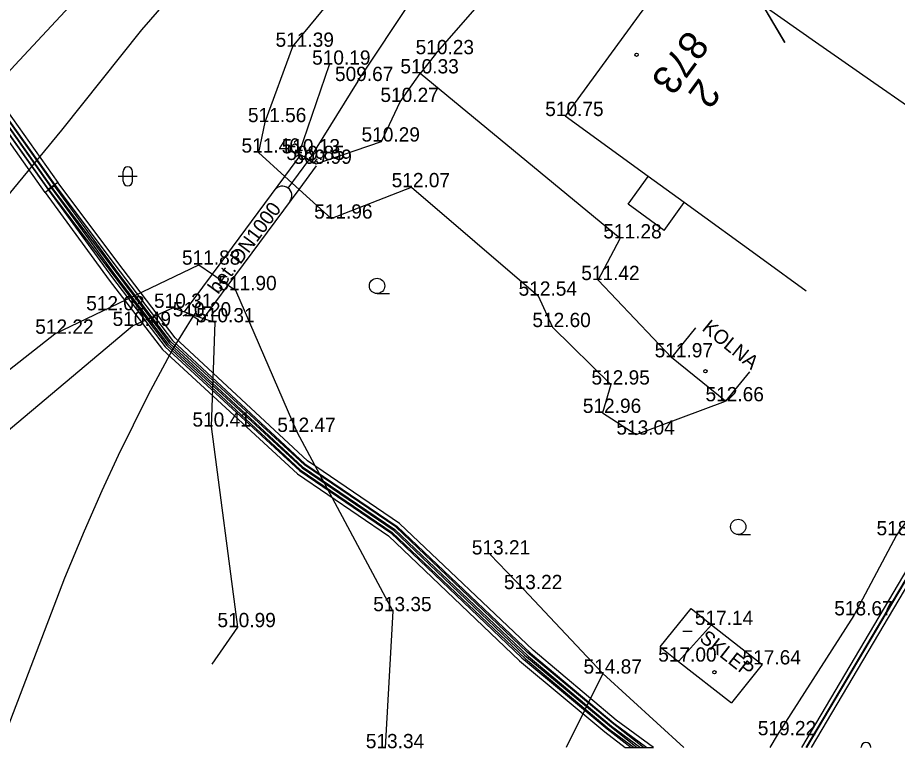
# Model space of a CAD drawing. Extents: x -669642 to -669119, y -1131006 to -1130466.
# Drawn here: x -669445.4 to -669399.17, y -1131000.64 to -1130962.24 of the extents above; entities that cross this region are included whole.
import ezdxf

# ---------------------------------------------------------------- set-up
doc = ezdxf.new("R2010")
doc.units = 0
for name, color, linetype in [('G_Bod_tecka', 7, 'Continuous'), ('G_Bod_vyska', 7, 'Continuous'), ('G_Breh_Teren', 7, 'Continuous'), ('G_Budovy-znacky', 7, 'Continuous'), ('G_Budovy_Objekty', 7, 'Continuous'), ('G_Budovy_vstupy', 7, 'Continuous'), ('G_Cesty_Schody', 7, 'Continuous'), ('G_Cisla_orientacni', 7, 'Continuous'), ('G_Cisla_popisna', 7, 'Continuous'), ('G_Ploty', 7, 'Continuous'), ('G_Ploty_vstupy', 7, 'Continuous'), ('G_Popisy_objektu', 7, 'Continuous'), ('G_Poznamky_odkaz', 7, 'Continuous'), ('G_Site-kanalizace', 7, 'Continuous'), ('G_Z_CHRANICKA-TEPLOVOD_kotovane', 7, 'Continuous'), ('G_Z_ELsilove_podz_kotovane', 7, 'Continuous'), ('G_Z_SPOJE_podz_kotovane', 7, 'Continuous'), ('G_Z_VODA_podz_kotovane', 7, 'Continuous'), ('G_Zelen-Znacky', 7, 'Continuous'), ('Vrstva 26', 7, 'Continuous')]:
    doc.layers.add(name, color=color, linetype=linetype)

msp = doc.modelspace()

# ---------------------------------------------------------------- linework, layer by layer
at = {"layer": 'G_Bod_tecka'}
for p, q in [((-669430.96, -1130963.77), (-669430.96, -1130963.77)), ((-669423.44, -1130964.16), (-669423.44, -1130964.16)), ((-669429.02, -1130964.71), (-669429.02, -1130964.71)), ((-669424.24, -1130965.17), (-669424.24, -1130965.17)), ((-669427.52, -1130965.57), (-669427.52, -1130965.57)), ((-669425.29, -1130966.67), (-669425.29, -1130966.67)), ((-669416.63, -1130967.41), (-669416.63, -1130967.41)), ((-669432.4, -1130967.73), (-669432.4, -1130967.73)), ((-669426.28, -1130968.75), (-669426.28, -1130968.75)), ((-669432.74, -1130969.33), (-669432.74, -1130969.33)), ((-669430.62, -1130969.37), (-669430.62, -1130969.37)), ((-669430.09, -1130969.72), (-669430.09, -1130969.72)), ((-669429.71, -1130969.92), (-669429.71, -1130969.92)), ((-669424.7, -1130971.15), (-669424.7, -1130971.15)), ((-669428.92, -1130972.8), (-669428.92, -1130972.8)), ((-669413.74, -1130973.84), (-669413.74, -1130973.84)), ((-669435.88, -1130975.22), (-669435.88, -1130975.22)), ((-669414.9, -1130976.03), (-669414.9, -1130976.03)), ((-669433.95, -1130976.56), (-669433.95, -1130976.56)), ((-669418.05, -1130976.85), (-669418.05, -1130976.85)), ((-669440.75, -1130977.62), (-669440.75, -1130977.62)), ((-669437.25, -1130977.49), (-669437.25, -1130977.49)), ((-669436.18, -1130977.94), (-669436.18, -1130977.94)), ((-669439.36, -1130978.44), (-669439.36, -1130978.44)), ((-669435.03, -1130978.25), (-669435.03, -1130978.25)), ((-669417.29, -1130978.5), (-669417.29, -1130978.5)), ((-669443.45, -1130978.85), (-669443.45, -1130978.85)), ((-669411.04, -1130980.09), (-669411.04, -1130980.09)), ((-669414.22, -1130981.52), (-669414.22, -1130981.52)), ((-669408.2, -1130982.4), (-669408.2, -1130982.4)), ((-669414.66, -1130983.01), (-669414.66, -1130983.01)), ((-669435.23, -1130983.73), (-669435.23, -1130983.73)), ((-669430.73, -1130984.01), (-669430.73, -1130984.01)), ((-669412.89, -1130984.15), (-669412.89, -1130984.15)), ((-669399.22, -1130989.44), (-669399.22, -1130989.44)), ((-669420.57, -1130990.45), (-669420.57, -1130990.45)), ((-669418.82, -1130992.27), (-669418.82, -1130992.27)), ((-669425.69, -1130993.43), (-669425.69, -1130993.43)), ((-669401.45, -1130993.65), (-669401.45, -1130993.65)), ((-669433.85, -1130994.27), (-669433.85, -1130994.27)), ((-669408.93, -1130994.15), (-669408.93, -1130994.15)), ((-669410.67, -1130996.08), (-669410.67, -1130996.08)), ((-669406.27, -1130996.23), (-669406.27, -1130996.23)), ((-669414.64, -1130996.71), (-669414.64, -1130996.71)), ((-669405.48, -1130999.95), (-669405.48, -1130999.95))]:
    msp.add_line(p, q, dxfattribs=at)
at = {"layer": 'G_Breh_Teren'}
for p, q in [((-669427.52, -1130965.57), (-669419.21, -1130953.1)), ((-669430.96, -1130963.77), (-669432.4, -1130967.73)), ((-669429.02, -1130964.71), (-669430.62, -1130969.37)), ((-669425.29, -1130966.67), (-669424.24, -1130965.17)), ((-669427.52, -1130965.57), (-669430.08, -1130969.7)), ((-669426.28, -1130968.75), (-669425.29, -1130966.67)), ((-669429.71, -1130969.92), (-669426.28, -1130968.75)), ((-669430.62, -1130969.37), (-669430.51, -1130969.44)), ((-669430.51, -1130969.44), (-669430.08, -1130969.7)), ((-669430.08, -1130969.7), (-669429.71, -1130969.92)), ((-669431.36, -1130970.59), (-669430.61, -1130971.27)), ((-669428.92, -1130972.8), (-669424.7, -1130971.15)), ((-669424.7, -1130971.15), (-669418.05, -1130976.85)), ((-669430.61, -1130971.27), (-669428.92, -1130972.8)), ((-669418.05, -1130976.85), (-669417.29, -1130978.5)), ((-669417.29, -1130978.5), (-669414.22, -1130981.52)), ((-669414.22, -1130981.52), (-669414.66, -1130983.01)), ((-669412.89, -1130984.15), (-669408.2, -1130982.4)), ((-669414.66, -1130983.01), (-669412.89, -1130984.15)), ((-669414.64, -1130996.71), (-669416.569, -1131000.6))]:
    msp.add_line(p, q, dxfattribs=at)
for points in [[(-669430.96, -1130963.77), (-669421.02, -1130951.72)], [(-669435.92, -1130954.59), (-669439.18, -1130957.99), (-669442.43, -1130961.39), (-669445.54, -1130964.74), (-669448.62, -1130968.12), (-669451.09, -1130970.63), (-669452.47, -1130971.73), (-669454.01, -1130972.63), (-669454.91, -1130972.96), (-669456.53, -1130973.24), (-669459.04, -1130973.32), (-669460.28, -1130973.4), (-669461.49, -1130973.64), (-669462.64, -1130973.98), (-669463.8, -1130974.32)], [(-669434.28, -1130957.66), (-669435.12, -1130958.57), (-669435.95, -1130959.48), (-669438.89, -1130962.88), (-669443.1, -1130968.15), (-669447.41, -1130973.39), (-669448.41, -1130974.47), (-669449.22, -1130975.22), (-669450.54, -1130976.2), (-669452.04, -1130976.89), (-669453.39, -1130977.17), (-669455.45, -1130977.27), (-669456.48, -1130977.33), (-669457.49, -1130977.5), (-669458.81, -1130977.82), (-669460.13, -1130978.14)], [(-669432.4, -1130967.73), (-669432.74, -1130969.33)], [(-669432.74, -1130969.33), (-669431.36, -1130970.59)], [(-669443.45, -1130978.85), (-669435.88, -1130975.22)], [(-669435.88, -1130975.22), (-669435.16, -1130975.72)], [(-669435.16, -1130975.72), (-669434.33, -1130976.29)], [(-669434.33, -1130976.29), (-669433.95, -1130976.56)], [(-669433.95, -1130976.56), (-669430.73, -1130984.01)], [(-669439.36, -1130978.44), (-669437.25, -1130977.49)], [(-669437.25, -1130977.49), (-669436.63, -1130977.7)], [(-669436.63, -1130977.7), (-669435.63, -1130978.04)], [(-669446.319, -1131000.6), (-669442.91, -1130991.68), (-669441.88, -1130989.21), (-669440.95, -1130987.08), (-669440.1, -1130985.23), (-669438.52, -1130982.04), (-669437.26, -1130979.7), (-669436.18, -1130977.94)], [(-669435.63, -1130978.04), (-669435.03, -1130978.25)], [(-669464.693, -1131000.6), (-669460.18, -1130996.71), (-669458.38, -1130995.11), (-669455.74, -1130992.64), (-669454.45, -1130991.37), (-669453.2, -1130990.07), (-669439.36, -1130978.44)], [(-669435.03, -1130978.25), (-669435.23, -1130983.73)], [(-669469.073, -1131000.6), (-669462.4, -1130994.41), (-669458.82, -1130990.94), (-669443.45, -1130978.85)], [(-669435.23, -1130983.73), (-669433.85, -1130994.27)], [(-669430.73, -1130984.01), (-669425.69, -1130993.43)], [(-669425.69, -1130993.43), (-669426.078, -1131000.6)], [(-669433.85, -1130994.27), (-669435.19, -1130996.22)]]:
    msp.add_lwpolyline(points, dxfattribs=at)
at = {"layer": 'G_Budovy-znacky'}
msp.add_line((-669410.45, -1130994.48), (-669409.95, -1130994.48), dxfattribs=at)
for centre in [(-669412.87, -1130964.19), (-669409.26, -1130980.821), (-669408.78, -1130996.641)]:
    msp.add_circle(centre, 0.0875, dxfattribs=at)
at = {"layer": 'G_Budovy_Objekty'}
for p, q in [((-669410.29, -1130958.73), (-669416.63, -1130967.41)), ((-669404.3, -1130962.95), (-669410.29, -1130958.73)), ((-669402.09, -1130964.49), (-669403.48, -1130963.52)), ((-669398.64, -1130966.89), (-669400.41, -1130965.66)), ((-669412.26, -1130970.58), (-669416.63, -1130967.41)), ((-669413.32, -1130972.04), (-669412.26, -1130970.58)), ((-669410.37, -1130971.96), (-669412.26, -1130970.58)), ((-669411.42, -1130973.42), (-669413.32, -1130972.04)), ((-669411.42, -1130973.42), (-669410.37, -1130971.96)), ((-669406.23, -1130974.96), (-669410.37, -1130971.96)), ((-669403.96, -1130976.61), (-669406.23, -1130974.96)), ((-669409.78, -1130978.54), (-669411.04, -1130980.09)), ((-669408.2, -1130982.4), (-669411.04, -1130980.09)), ((-669406.94, -1130980.85), (-669408.2, -1130982.4)), ((-669411.63, -1130995.31), (-669410, -1130993.29)), ((-669410, -1130993.29), (-669408.93, -1130994.15)), ((-669410.67, -1130996.08), (-669408.93, -1130994.15)), ((-669408.93, -1130994.15), (-669406.27, -1130996.23)), ((-669411.63, -1130995.31), (-669410.67, -1130996.08)), ((-669410.67, -1130996.08), (-669407.89, -1130998.25)), ((-669406.27, -1130996.23), (-669407.89, -1130998.25))]:
    msp.add_line(p, q, dxfattribs=at)
at = {"layer": 'G_Budovy_vstupy'}
for p, q in [((-669403.48, -1130963.52), (-669404.3, -1130962.95)), ((-669400.41, -1130965.66), (-669402.09, -1130964.49))]:
    msp.add_line(p, q, dxfattribs=at)
at = {"layer": 'G_Cesty_Schody'}
for p, q in [((-669431.36, -1130970.59), (-669430.51, -1130969.44)), ((-669430.61, -1130971.27), (-669429.69, -1130970.02)), ((-669435.16, -1130975.72), (-669431.36, -1130970.59)), ((-669434.33, -1130976.29), (-669430.61, -1130971.27)), ((-669436.63, -1130977.7), (-669435.16, -1130975.72)), ((-669435.63, -1130978.04), (-669434.33, -1130976.29)), ((-669435.78, -1130978.24), (-669435.63, -1130978.04))]:
    msp.add_line(p, q, dxfattribs=at)
at = {"layer": 'G_Ploty'}
for p, q in [((-669423.44, -1130964.16), (-669421.37, -1130961.8)), ((-669413.74, -1130973.84), (-669424.24, -1130965.17)), ((-669414.9, -1130976.03), (-669413.74, -1130973.84)), ((-669411.04, -1130980.09), (-669414.9, -1130976.03)), ((-669396.12, -1130985.05), (-669399.22, -1130989.44)), ((-669399.22, -1130989.44), (-669401.45, -1130993.65)), ((-669418.82, -1130992.27), (-669420.57, -1130990.45)), ((-669414.64, -1130996.71), (-669418.82, -1130992.27)), ((-669401.45, -1130993.65), (-669405.48, -1130999.95)), ((-669410.395, -1131000.6), (-669414.64, -1130996.71)), ((-669405.48, -1130999.95), (-669405.871, -1131000.6))]:
    msp.add_line(p, q, dxfattribs=at)
at = {"layer": 'G_Ploty_vstupy'}
msp.add_line((-669423.44, -1130964.16), (-669424.24, -1130965.17), dxfattribs=at)
at = {"layer": 'G_Site-kanalizace'}
for p, q in [((-669430.151, -1130969.301), (-669430.33, -1130969.541)), ((-669431.188, -1130971.192), (-669430.09, -1130969.72)), ((-669430.33, -1130969.541), (-669430.09, -1130969.72)), ((-669429.85, -1130969.899), (-669430.09, -1130969.72)), ((-669429.671, -1130969.659), (-669429.85, -1130969.899))]:
    msp.add_line(p, q, dxfattribs=at)
for points in [[(-669436.017, -1130977.688), (-669436.18, -1130977.94)], [(-669436.699, -1130977.914), (-669436.432, -1130977.777)], [(-669436.18, -1130977.94), (-669436.432, -1130977.777)], [(-669435.928, -1130978.103), (-669436.18, -1130977.94)], [(-669435.943, -1130978.403), (-669435.928, -1130978.103)]]:
    msp.add_lwpolyline(points, dxfattribs=at)
msp.add_arc((-669431.487, -1130971.593), 0.5, 323.2668, 143.2668, dxfattribs=at)
at = {"layer": 'G_Z_CHRANICKA-TEPLOVOD_kotovane'}
for p, q in [((-669413.481, -1131000.6), (-669412.514, -1131000.6)), ((-669413.005, -1131000.6), (-669411.992, -1131000.6))]:
    msp.add_line(p, q, dxfattribs=at)
for points in [[(-669449.293, -1130963.042), (-669449.036, -1130962.88), (-669449.027, -1130962.894), (-669447.101, -1130965.943), (-669443.481, -1130971.042), (-669443.479, -1130971.044), (-669443.46, -1130971.071), (-669443.456, -1130971.077), (-669443.75, -1130971.286), (-669443.945, -1130971.424), (-669447.59, -1130966.29), (-669449.544, -1130963.2), (-669449.337, -1130963.07)], [(-669449.084, -1130962.785), (-669448.886, -1130962.661), (-669448.877, -1130962.675), (-669446.881, -1130965.863), (-669443.291, -1130970.899), (-669443.286, -1130970.906), (-669443.479, -1130971.044), (-669443.553, -1130971.096), (-669443.774, -1130971.254), (-669447.389, -1130966.181), (-669449.337, -1130963.07), (-669449.339, -1130963.066), (-669449.394, -1130962.979), (-669449.14, -1130962.82)]]:
    msp.add_lwpolyline(points, close=True, dxfattribs=at)
for points in [[(-669412.514, -1131000.6), (-669414.161, -1130999.297), (-669418.63, -1130995.586), (-669425.531, -1130988.996), (-669430.323, -1130985.734), (-669437.348, -1130979.267), (-669440.1, -1130975.68), (-669443.46, -1130971.071), (-669443.752, -1130971.284), (-669443.945, -1130971.424), (-669440.585, -1130976.033), (-669437.792, -1130979.673), (-669430.697, -1130986.206), (-669425.909, -1130989.464), (-669419.03, -1130996.034), (-669414.539, -1130999.763), (-669413.481, -1131000.6)], [(-669411.992, -1131000.6), (-669413.944, -1130999.164), (-669418.31, -1130995.486), (-669425.331, -1130988.826), (-669430.172, -1130985.525), (-669437.117, -1130979.068), (-669439.851, -1130975.469), (-669443.291, -1130970.899), (-669443.481, -1130971.042), (-669443.553, -1130971.096), (-669443.77, -1130971.26), (-669443.752, -1130971.284), (-669443.75, -1130971.286), (-669440.33, -1130975.83), (-669437.563, -1130979.472), (-669430.548, -1130985.995), (-669425.709, -1130989.294), (-669418.71, -1130995.934), (-669414.316, -1130999.636), (-669413.005, -1131000.6)]]:
    msp.add_lwpolyline(points, dxfattribs=at)
at = {"layer": 'G_Z_ELsilove_podz_kotovane'}
for points in [[(-669461.85, -1130874.357), (-669460.68, -1130889.299), (-669459.729, -1130899.044), (-669459.61, -1130899.661), (-669459.56, -1130901.616), (-669458.21, -1130916.364), (-669458.25, -1130919.053), (-669456.94, -1130934.617), (-669456.049, -1130949.368), (-669454.16, -1130955.298), (-669452.214, -1130957.705), (-669449.377, -1130963.09), (-669447.433, -1130966.166), (-669443.781, -1130971.308), (-669440.42, -1130975.92), (-669437.644, -1130979.538), (-669430.572, -1130986.049), (-669425.783, -1130989.308), (-669418.897, -1130995.885), (-669414.413, -1130999.608), (-669413.159, -1131000.6)], [(-669461.65, -1130874.343), (-669460.48, -1130889.281), (-669459.531, -1130899.016), (-669459.41, -1130899.639), (-669459.36, -1130901.604), (-669458.01, -1130916.356), (-669458.05, -1130919.047), (-669456.74, -1130934.603), (-669455.851, -1130949.332), (-669453.98, -1130955.202), (-669452.046, -1130957.595), (-669449.203, -1130962.99), (-669447.267, -1130966.054), (-669443.619, -1130971.192), (-669440.26, -1130975.8), (-669437.496, -1130979.402), (-669430.448, -1130985.891), (-669425.657, -1130989.152), (-669418.763, -1130995.735), (-669414.287, -1130999.452), (-669412.836, -1131000.6)], [(-669403.922, -1131000.6), (-669397.895, -1130990.437), (-669392.449, -1130982.107), (-669389.976, -1130979.544), (-669386.44, -1130978.204), (-669377.787, -1130976.089), (-669371.474, -1130976.672), (-669366.225, -1130979.055), (-669357.585, -1130986.614), (-669346.334, -1130996.265), (-669341.42, -1131000.6)], [(-669403.689, -1131000.6), (-669397.725, -1130990.543), (-669392.291, -1130982.233), (-669389.864, -1130979.716), (-669386.38, -1130978.396), (-669377.773, -1130976.291), (-669371.526, -1130976.868), (-669366.335, -1130979.225), (-669357.715, -1130986.766), (-669346.466, -1130996.415), (-669341.721, -1131000.6)]]:
    msp.add_lwpolyline(points, dxfattribs=at)
at = {"layer": 'G_Z_SPOJE_podz_kotovane'}
for points in [[(-669458.529, -1130909.31), (-669458.18, -1130912.388), (-669457.97, -1130916.355), (-669457.86, -1130919.006), (-669456.59, -1130934.547), (-669455.709, -1130949.33), (-669453.749, -1130954.978), (-669451.845, -1130957.423), (-669449.228, -1130962.868), (-669447.213, -1130966.086), (-669443.611, -1130971.139), (-669440.17, -1130975.71), (-669437.414, -1130979.337), (-669430.423, -1130985.838), (-669425.583, -1130989.138), (-669418.577, -1130995.785), (-669414.192, -1130999.479), (-669412.668, -1131000.6)], [(-669458.529, -1130909.31), (-669458.18, -1130912.388), (-669457.97, -1130916.355), (-669457.86, -1130919.006), (-669456.59, -1130934.547), (-669455.709, -1130949.33), (-669453.749, -1130954.978), (-669451.845, -1130957.423), (-669449.228, -1130962.868), (-669447.213, -1130966.086), (-669443.611, -1130971.139), (-669440.17, -1130975.71), (-669437.414, -1130979.337), (-669430.423, -1130985.838), (-669425.583, -1130989.138), (-669418.577, -1130995.785), (-669414.192, -1130999.479), (-669412.668, -1131000.6)], [(-669457.98, -1130912.372), (-669457.77, -1130916.345), (-669457.66, -1130918.994), (-669456.39, -1130934.533), (-669455.511, -1130949.29), (-669453.571, -1130954.882), (-669451.675, -1130957.317), (-669449.052, -1130962.772), (-669447.047, -1130965.974), (-669443.449, -1130971.021), (-669440.01, -1130975.59), (-669437.266, -1130979.203), (-669430.297, -1130985.682), (-669425.457, -1130988.982), (-669418.443, -1130995.635), (-669414.068, -1130999.321), (-669412.329, -1131000.6)], [(-669404.197, -1131000.6), (-669398.095, -1130990.297), (-669392.609, -1130981.908), (-669390.237, -1130979.314), (-669386.469, -1130977.974), (-669377.757, -1130975.779), (-669371.423, -1130976.502), (-669366.085, -1130978.905), (-669357.435, -1130986.434), (-669346.124, -1130996.045), (-669341.017, -1131000.6)], [(-669403.963, -1131000.6), (-669397.925, -1130990.403), (-669392.451, -1130982.032), (-669390.123, -1130979.486), (-669386.411, -1130978.166), (-669377.743, -1130975.981), (-669371.477, -1130976.698), (-669366.195, -1130979.075), (-669357.565, -1130986.586), (-669346.256, -1130996.195), (-669341.318, -1131000.6)], [(-669403.963, -1131000.6), (-669397.925, -1130990.403), (-669392.451, -1130982.032), (-669390.123, -1130979.486), (-669386.411, -1130978.166), (-669377.743, -1130975.981), (-669371.477, -1130976.698), (-669366.195, -1130979.075), (-669357.565, -1130986.586), (-669346.256, -1130996.195), (-669341.318, -1131000.6)]]:
    msp.add_lwpolyline(points, dxfattribs=at)
at = {"layer": 'G_Z_VODA_podz_kotovane'}
msp.add_lwpolyline([(-669412.19, -1130940.54), (-669412.05, -1130940.72), (-669411.99, -1130940.91), (-669410.68, -1130947.61), (-669408.63, -1130954.5), (-669408.29, -1130956.23), (-669407.79, -1130958.1), (-669406.89, -1130960.49), (-669405.09, -1130963.54)], dxfattribs=at)
at = {"layer": 'G_Zelen-Znacky'}
for p, q in [((-669426.512, -1130976.74), (-669425.862, -1130976.737)), ((-669407.532, -1130989.4), (-669406.882, -1130989.397)), ((-669401.07, -1131000.6), (-669401.07, -1131000.58)), ((-669400.57, -1131000.6), (-669400.57, -1131000.58))]:
    msp.add_line(p, q, dxfattribs=at)
for points in [[(-669439.11, -1130970.58), (-669440.11, -1130970.58)], [(-669439.86, -1130970.83), (-669439.86, -1130970.33)], [(-669439.36, -1130970.83), (-669439.36, -1130970.33)]]:
    msp.add_lwpolyline(points, dxfattribs=at)
for centre in [(-669426.512, -1130976.337), (-669407.532, -1130988.998)]:
    msp.add_circle(centre, 0.403, dxfattribs=at)
for centre, start, end in [((-669439.609, -1130970.33), 0, 180), ((-669439.609, -1130970.83), 180, 0), ((-669400.819, -1131000.58), 0, 180)]:
    msp.add_arc(centre, 0.25, start, end, dxfattribs=at)
at = {"layer": 'Vrstva 26'}
msp.add_lwpolyline([(-669412.19, -1130940.54), (-669412.05, -1130940.72), (-669411.99, -1130940.91), (-669410.68, -1130947.61), (-669408.63, -1130954.5), (-669408.29, -1130956.23), (-669407.79, -1130958.1), (-669406.893, -1130960.491), (-669405.094, -1130963.536)], dxfattribs=at)

# ---------------------------------------------------------------- texts
at = {"layer": 'G_Bod_vyska'}
for s, p in [('511.39', (-669431.843, -1130963.77)), ('510.23', (-669424.484, -1130964.16)), ('510.19', (-669429.924, -1130964.71)), ('510.33', (-669425.284, -1130965.17)), ('509.67', (-669428.721, -1130965.57)), ('510.27', (-669426.334, -1130966.67)), ('511.56', (-669433.294, -1130967.73)), ('510.75', (-669417.674, -1130967.41)), ('510.29', (-669427.326, -1130968.75)), ('511.46', (-669433.634, -1130969.33)), ('510.13', (-669431.522, -1130969.37)), ('509.85', (-669431.278, -1130969.72)), ('509.99', (-669430.902, -1130969.92)), ('512.07', (-669425.744, -1130971.15)), ('511.96', (-669429.816, -1130972.8)), ('511.28', (-669414.621, -1130973.84)), ('511.88', (-669436.761, -1130975.22)), ('511.42', (-669415.781, -1130976.03)), ('511.90', (-669434.854, -1130976.56)), ('512.54', (-669419.072, -1130976.85)), ('510.31', (-669438.232, -1130977.49)), ('512.03', (-669441.794, -1130977.62)), ('510.20', (-669437.246, -1130977.94)), ('510.49', (-669440.406, -1130978.44)), ('510.31', (-669436.012, -1130978.25)), ('512.22', (-669444.472, -1130978.85)), ('512.60', (-669418.348, -1130978.5)), ('511.97', (-669411.923, -1130980.09)), ('512.95', (-669415.244, -1130981.52)), ('512.66', (-669409.25, -1130982.4)), ('512.96', (-669415.698, -1130983.01)), ('510.41', (-669436.212, -1130983.73)), ('512.47', (-669431.752, -1130984.01)), ('513.04', (-669413.934, -1130984.15)), ('518.40', (-669400.264, -1130989.44)), ('513.21', (-669421.531, -1130990.45)), ('513.22', (-669419.842, -1130992.27)), ('513.35', (-669426.712, -1130993.43)), ('518.67', (-669402.486, -1130993.65)), ('517.14', (-669409.811, -1130994.15)), ('510.99', (-669434.898, -1130994.27)), ('517.00', (-669411.736, -1130996.08)), ('517.64', (-669407.306, -1130996.23)), ('514.87', (-669415.662, -1130996.71)), ('519.22', (-669406.504, -1130999.95)), ('513.34', (-669427.102, -1131000.63))]:
    msp.add_text(s, height=0.75, dxfattribs=at).set_placement(p)
at = {"layer": 'G_Cisla_orientacni'}
msp.add_text('2', height=1.5, rotation=234.0148, dxfattribs=at).set_placement((-669409.574, -1130965.345))
at = {"layer": 'G_Cisla_popisna'}
msp.add_text('873', height=1.5, rotation=233.8462, dxfattribs=at).set_placement((-669410.189, -1130962.819))
at = {"layer": 'G_Popisy_objektu'}
for s, rotation, p in [('KOLNA', 320.8758, (-669409.482, -1130978.634)), ('SKLEP', 321.9797, (-669409.618, -1130994.958))]:
    msp.add_text(s, height=0.75, rotation=rotation, dxfattribs=at).set_placement(p)
at = {"layer": 'G_Poznamky_odkaz'}
msp.add_text('bet. DN1000', height=0.75, rotation=53.4616, dxfattribs=at).set_placement((-669434.861, -1130976.814))

doc.saveas('drawing.dxf')
